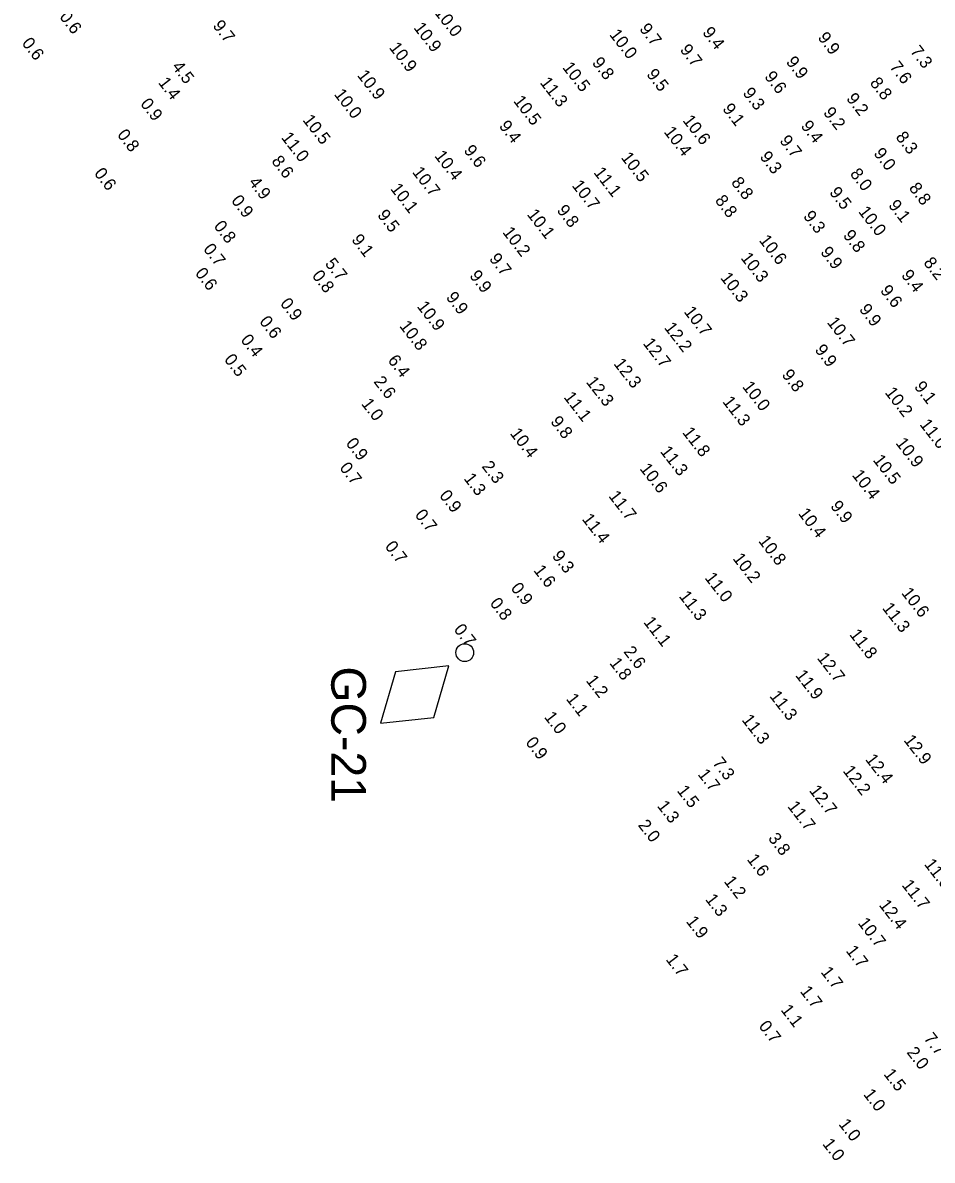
# Model space of a CAD drawing. Extents: x 815385 to 820851, y 582449 to 604245.
# Drawn here: x 818662.8 to 819030.1, y 594117 to 594576.2 of the extents above; entities that cross this region are included whole.
import ezdxf

# ---------------------------------------------------------------- set-up
doc = ezdxf.new("R2010")
doc.units = 0
for name, color, linetype in [('V-CHAN-AIDS', 7, 'Continuous'), ('V-TOPO-SOUN-011609', 7, 'Continuous'), ('V-TOPO-SOUN-020509C', 7, 'Continuous'), ('V-TOPO-SOUN-EXCSS', 7, 'Continuous')]:
    doc.layers.add(name, color=color, linetype=linetype)

msp = doc.modelspace()

# ---------------------------------------------------------------- linework, layer by layer
at = {"layer": 'V-CHAN-AIDS'}
msp.add_lwpolyline([(818834.86, 594316.55), (818813.35, 594314.17), (818807.28, 594293.41), (818828.78, 594295.79)], close=True, dxfattribs=at)
msp.add_circle((818841.29, 594321.95), 3.6, dxfattribs=at)

# ---------------------------------------------------------------- texts
msp.add_text('GC-21', height=14, rotation=270, dxfattribs=at).set_placement((818787.39, 594316.37))
at = {"layer": 'V-TOPO-SOUN-011609'}
for s, p in [('9.4', (818937.04, 594572.25)), ('9.7', (818927.98, 594565.25)), ('7.3', (819020.99, 594564.65)), ('7.6', (819012.66, 594558.35)), ('8.8', (819004.69, 594551.87)), ('9.2', (818995.16, 594545.56)), ('9.2', (818985.85, 594539.87)), ('9.4', (818976.79, 594534.46)), ('9.7', (818968.21, 594528.52)), ('9.3', (818960.21, 594522.03)), ('8.8', (819020.45, 594509.41)), ('9.1', (819012.15, 594502.46)), ('10.0 ', (819000.04, 594499.92)), ('9.8', (818993.84, 594490.31)), ('9.9', (818984.71, 594483.54)), ('9.1', (819022.58, 594429.22))]:
    msp.add_text(s, height=5, rotation=307.782, dxfattribs=at).set_placement(p)
at = {"layer": 'V-TOPO-SOUN-020509C'}
for s, p in [('0.6', (818677.37, 594578.54)), ('10.0 ', (818828.78, 594580.33)), ('9.7', (818739.28, 594574.97)), ('10.9 ', (818820.43, 594574.14)), ('10.0 ', (818899.49, 594571.39)), ('0.6', (818662.19, 594567.93)), ('10.9 ', (818810.55, 594566.11)), ('9.8', (818892.45, 594560.05)), ('4.5', (818722.79, 594558.42)), ('10.5 ', (818880.51, 594558.13)), ('1.4', (818717.29, 594551.97)), ('10.9 ', (818797.64, 594554.93)), ('11.3 ', (818871.43, 594552)), ('10.0 ', (818788.29, 594547.29)), ('0.9', (818710.05, 594543.42)), ('10.5 ', (818860.7, 594544.59)), ('10.5 ', (818775.61, 594536.9)), ('9.4', (818854.89, 594534.47)), ('10.6 ', (818929.1, 594536.72)), ('0.8', (818700.7, 594530.94)), ('11.0 ', (818766.96, 594529.81)), ('10.4 ', (818921.49, 594532.11)), ('9.6', (818840.65, 594524.59)), ('8.6', (818763.02, 594520.27)), ('10.4 ', (818828.85, 594522.41)), ('10.5 ', (818904.17, 594521.75)), ('0.6', (818691.39, 594515.35)), ('10.7 ', (818819.88, 594515.86)), ('11.1 ', (818893.13, 594515.71)), ('4.9', (818753.77, 594511.72)), ('10.7 ', (818884.35, 594510.46)), ('10.1 ', (818811.05, 594509.15)), ('0.9', (818746.75, 594504.33)), ('9.8', (818878.24, 594500.42)), ('9.5', (818805.76, 594498.49)), ('10.1 ', (818866.23, 594498.77)), ('0.8', (818739.71, 594494.04)), ('10.2 ', (818856.33, 594491.6)), ('9.1', (818795.35, 594488.57)), ('10.6 ', (818959.9, 594488.35)), ('0.7', (818735.47, 594484.77)), ('5.7', (818784.61, 594478.89)), ('9.7', (818850.95, 594480.87)), ('10.3 ', (818952.51, 594481.23)), ('0.6', (818732.16, 594475.02)), ('0.8', (818779.37, 594474.03)), ('9.9', (818842.98, 594474.01)), ('10.3 ', (818944.32, 594473.19)), ('9.9', (818833.49, 594465.3)), ('0.9', (818766.5, 594462.79)), ('10.9 ', (818821.79, 594461.63)), ('10.7 ', (818929.56, 594459.51)), ('0.6', (818758.11, 594455.56)), ('10.7 ', (818987.39, 594455.19)), ('10.8 ', (818814.68, 594453.73)), ('12.2 ', (818921.64, 594453.06)), ('0.4', (818750.57, 594448.12)), ('12.7 ', (818913.04, 594446.71)), ('9.9', (818982.44, 594444.09)), ('0.5', (818743.89, 594440.21)), ('6.4', (818809.98, 594439.87)), ('12.3 ', (818901.2, 594438.51)), ('2.6', (818804.29, 594431.27)), ('9.8', (818969.1, 594434.02)), ('12.3 ', (818890.06, 594431.14)), ('10.0 ', (818953.17, 594429.24)), ('1.0', (818799.3, 594422.34)), ('11.1 ', (818881.03, 594425.02)), ('11.3 ', (818945.18, 594423.2)), ('9.8', (818875.68, 594415.14)), ('11.0 ', (819024.8, 594414)), ('10.4 ', (818859.34, 594410.38)), ('11.8 ', (818928.96, 594410.78)), ('0.9', (818793.04, 594406.35)), ('10.9 ', (819015.11, 594406.48)), ('11.3 ', (818919.98, 594403.11)), ('10.5 ', (819005.92, 594399.64)), ('0.7', (818790.49, 594396.49)), ('2.3', (818847.94, 594397.07)), ('10.6 ', (818911.75, 594396.14)), ('1.3', (818840.68, 594392.16)), ('10.4 ', (818997.49, 594393.56)), ('0.9', (818830.81, 594385.28)), ('11.7 ', (818899.15, 594385.08)), ('9.9', (818988.72, 594380.99)), ('0.7', (818820.92, 594377.5)), ('10.4 ', (818975.75, 594378.06)), ('11.4 ', (818888.41, 594375.82)), ('0.7', (818808.83, 594364.73)), ('10.8 ', (818959.65, 594366.96)), ('9.3', (818876.32, 594360.89)), ('10.2 ', (818949.3, 594359.88)), ('1.6', (818868.86, 594355.09)), ('11.0 ', (818937.98, 594352.08)), ('0.9', (818859.65, 594347.91)), ('11.3 ', (818927.57, 594344.64)), ('10.6 ', (819017.42, 594345.97)), ('0.8', (818851.2, 594341.8)), ('11.3 ', (819009.68, 594339.87)), ('0.7', (818836.64, 594331.22)), ('11.1 ', (818913.24, 594334.21)), ('11.8 ', (818996.44, 594329.2)), ('2.6', (818905.23, 594322.26)), ('1.8', (818899.51, 594317.67)), ('12.7 ', (818983.35, 594319.71)), ('11.9 ', (818974.57, 594312.77)), ('1.2', (818890.02, 594310.61)), ('1.1', (818882.01, 594303.2)), ('11.3 ', (818964.16, 594304.35)), ('1.0', (818873.16, 594295.89)), ('11.3 ', (818952.95, 594294.75)), ('0.9', (818865.61, 594285.61)), ('12.9 ', (819018.34, 594286.54)), ('7.3', (818941.14, 594277.36)), ('12.4 ', (819002.84, 594278.78)), ('1.7', (818935.19, 594272.74)), ('12.2 ', (818993.78, 594274.15)), ('12.7 ', (818980.18, 594266.19)), ('1.5', (818926.78, 594266.14)), ('1.3', (818918.79, 594259.97)), ('11.7 ', (818971.43, 594259.81)), ('2.0', (818911.06, 594252.24)), ('3.8', (818963.61, 594246.9)), ('1.6', (818955.04, 594238.42)), ('11.0 ', (819026.61, 594236.48)), ('1.2', (818945.75, 594229.53)), ('11.7 ', (819017.57, 594228.05)), ('1.3', (818938.22, 594222.29)), ('12.4 ', (819008.34, 594220.01)), ('1.9', (818930.46, 594213.37)), ('10.7 ', (818999.84, 594212.71)), ('1.7', (818922.27, 594198.04)), ('1.7', (818995, 594201.51)), ('1.7', (818984.85, 594192.94)), ('1.7', (818976.46, 594185.18)), ('1.1', (818968.72, 594177.63)), ('0.7', (818959.79, 594171.09)), ('7.7', (819026.44, 594166.13)), ('2.0', (819019.57, 594160.51)), ('1.5', (819010.24, 594151.73)), ('1.0', (819002.04, 594143.6)), ('1.0', (818992.06, 594131.52)), ('1.0', (818985.53, 594123.56))]:
    msp.add_text(s, height=5, rotation=307.782, dxfattribs=at).set_placement(p)
at = {"layer": 'V-TOPO-SOUN-EXCSS'}
for s, p in [('9.7', (818911.59, 594573.68)), ('9.9', (818983.64, 594570.16)), ('9.9', (818970.8, 594560.36)), ('9.5', (818914.46, 594555.33)), ('9.6', (818962.09, 594554.41)), ('9.3', (818953.32, 594547.78)), ('9.1', (818945.16, 594541.38)), ('8.3', (819015.09, 594530.02)), ('9.0', (819006.19, 594523.41)), ('8.0', (818996.66, 594515.15)), ('8.8', (818948.66, 594511.66)), ('9.5', (818988.31, 594507.65)), ('8.8', (818942.13, 594504.39)), ('9.3', (818977.77, 594498.04)), ('8.2', (819026.34, 594479.28)), ('9.4', (819017.36, 594474.23)), ('9.6', (819008.85, 594468.04)), ('9.9', (819000.37, 594460.44)), ('10.2 ', (819010.74, 594426.89))]:
    msp.add_text(s, height=5, rotation=307.782, dxfattribs=at).set_placement(p)

doc.saveas('drawing.dxf')
